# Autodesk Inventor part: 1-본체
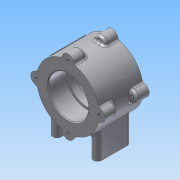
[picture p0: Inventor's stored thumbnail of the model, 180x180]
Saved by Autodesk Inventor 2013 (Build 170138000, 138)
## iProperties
Created: 2015-03
Part Number: 1-본체
Material: 알루미늄 6061
Document SubType Name: Modeling
Designer: ST4
Density: 2.71 g/cm^3
Mass: 450.778 g
Surface Area: 332.744 cm^2
Volume: 166.339 cm^3
Author: ST4
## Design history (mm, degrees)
sketch "스케치1"
  geometry: C1 r 37 at (0, 0); 1 further point
  constraints: 1 centre point, 1 coincident
  dimensions: "d0" = 74 diameter of C1
extrude "돌출1" new body sketch "스케치1" stored distance "d2" = 52; taper "d3" = 0 deg
sketch "스케치2"
  geometry: C1 r 7 at (0, 37); C2 r 7 at (-37, 0); C3 r 7 at (0, -37); C4 r 7 at (37, 0); A1 r 37 centre (0, 0) between (0, 37) and (-37, 0) reference; A2 r 37 centre (0, 0) between (0, 37) and (-37, 0)
  constraints: 8 point on circle, 5 centre point, 4 equal radius, 2 horizontal alignment, 2 vertical alignment, 1 coincident
  dimensions: "d4" = 14 diameter of C1
extrude "돌출2" join sketch "스케치2" distance "d6" = 15; taper "d7" = 0 deg
sketch "스케치3"
  geometry: A1 r 7 centre (0, 37) between (6.969, 36.338) and (-6.969, 36.338) reference; A2 r 7 centre (-37, 0) between (-36.338, 6.969) and (-36.338, -6.969) reference; A3 r 7 centre (0, -37) between (-6.969, -36.338) and (6.969, -36.338) reference; A4 r 7 centre (37, 0) between (36.338, -6.969) and (36.338, 6.969) reference; 4 further points
  constraints: 4 coincident
hole "구멍1" sketch "스케치3" at (0, 37), (37, 0), (0, -37), (-37, 0) diameter "d8" = 3.242; stored, may be unused: countersink angle "d12" = 90 deg, drill point angle "d14" = 118 deg; dims "d9" = 8, "d10" = 4, "d11" = 2, "d13" = 11
sketch "스케치4"
  geometry: C1 r 23.5 at (0, 0); A1 r 37 centre (0, 0) between (6.969, -36.338) and (36.338, -6.969) reference
  constraints: 1 centre point, 1 coincident
  dimensions: "d15" = 47 diameter of C1
extrude "돌출3" cut sketch "스케치4" distance "d17" = 22; taper "d18" = 0 deg
sketch "스케치5"
  geometry: C1 r 23.5 at (0, 0) reference; C2 r 21 at (0, 0)
  constraints: 1 centre point, 1 coincident
  dimensions: "d19" = 42 diameter of C2
extrude "돌출4" cut sketch "스케치5" stored distance "d21" = 22; taper "d22" = 0 deg
fillet "모깎기1" dims "d23" = 0.3
chamfer "모따기1" distance "d24" = 1; stored, may be unused: second distance "d25" = 2, angle "d26" = 45 deg
fillet "모깎기2" dims "d27" = 3
fillet "모깎기3" dims "d28" = 3
node "작업 평면1"
sketch "스케치6"
  geometry: L1 (-29, 15)-(-29, -15); L2 (-19, -15)-(-19, 15); L3 (19, 15)-(19, -15); L4 (29, -15)-(29, 15); L5 (-19, 0)-(19, 0); A1 r 5 centre (-24, -15) between (-29, -15) and (-19, -15); A2 r 5 centre (-24, 15) between (-19, 15) and (-29, 15); A3 r 5 centre (24, -15) between (19, -15) and (29, -15); A4 r 5 centre (24, 15) between (29, 15) and (19, 15); 2 further points
  constraints: 10 end point, 8 point on circle, 8 tangent, 4 centre point, 4 parallel, 3 midpoint, 2 horizontal alignment, 1 coincident, 1 equal radius, 1 perpendicular, 1 vertical
  dimensions: "d30" = 5 radius of A2; "d32" = 30 distance of A3.centre A4.centre; "d33" = 38 distance of L5.start L5.end
extrude "돌출5" join sketch "스케치6" stored distance "d34" = 22; taper "d35" = 0 deg
fillet "모깎기4" dims "d36" = 3
sketch "스케치7"
  geometry: L1 (-29, 15)-(-29, -15) reference; L2 (-19, -15)-(-19, 15) reference; A1 r 5 centre (24, -15) between (19, -15) and (29, -15) reference; A2 r 5 centre (24, 15) between (29, 15) and (19, 15) reference; A3 r 5 centre (-24, -15) between (-29, -15) and (-19, -15) reference; A4 r 5 centre (-24, 15) between (-19, 15) and (-29, 15) reference; 5 further points
  constraints: 4 coincident
hole "구멍2" sketch "스케치7" at (-24, 15), (-24, -15), (24, -15), (24, 15) diameter "d37" = 4.134; stored, may be unused: countersink angle "d41" = 90 deg, drill point angle "d43" = 118 deg; dims "d38" = 6, "d39" = 4, "d40" = 2, "d42" = 8
sketch "스케치8"
  geometry: C1 r 1.621 at (0, -37) reference; C2 r 1.621 at (0, 37) reference; C3 r 1.621 at (37, 0) reference; C4 r 1.621 at (-37, 0) reference; C5 r 24.5 at (0, 0) reference; A1 r 37 centre (0, 0) between (9.104, -35.863) and (35.863, -9.104) reference; A2 r 3 centre (9.842, -38.77) between (9.104, -35.863) and (6.889, -38.239) reference; A3 r 7 centre (0, -37) between (-6.889, -38.239) and (6.889, -38.239) reference; A4 r 3 centre (-9.842, -38.77) between (-6.889, -38.239) and (-9.104, -35.863) reference; A5 r 37 centre (0, 0) between (-35.863, -9.104) and (-9.104, -35.863) reference; A6 r 3 centre (-38.77, -9.842) between (-35.863, -9.104) and (-38.239, -6.889) reference; A7 r 7 centre (-37, 0) between (-38.239, 6.889) and (-38.239, -6.889) reference; A8 r 3 centre (-38.77, 9.842) between (-38.239, 6.889) and (-35.863, 9.104) reference; A9 r 37 centre (0, 0) between (-9.104, 35.863) and (-35.863, 9.104) reference; A10 r 3 centre (-9.842, 38.77) between (-9.104, 35.863) and (-6.889, 38.239) reference; A11 r 7 centre (0, 37) between (6.889, 38.239) and (-6.889, 38.239) reference; A12 r 3 centre (9.842, 38.77) between (6.889, 38.239) and (9.104, 35.863) reference; A13 r 37 centre (0, 0) between (35.863, 9.104) and (9.104, 35.863) reference; A14 r 3 centre (38.77, 9.842) between (35.863, 9.104) and (38.239, 6.889) reference; A15 r 7 centre (37, 0) between (38.239, -6.889) and (38.239, 6.889) reference; A16 r 3 centre (38.77, -9.842) between (38.239, -6.889) and (35.863, -9.104) reference; 2 further points
  constraints: 1 point on circle
  dimensions: "d44" = 45 deg dimension on point (0, 0) A7.centre point (-26.163, 26.163)
  node "투영된 루프2"
node "작업 평면2"
sketch "스케치9"
  geometry: L1 (-18.921, -26)-(18.921, -26) reference; L2 (18.921, 26)-(-18.921, 26) reference; 3 further points
  constraints: 1 midpoint, 1 vertical alignment, 1 other
  dimensions: "d45" = 26 distance from line of L1 point (0, 0)
feature "엠보싱1" sketch "스케치9" dims "d46" = 0.5, "d47" = 0
node "솔리드1"
mirror "대칭1"
node "투영된 루프1"
other parameters: "d29" = -56
